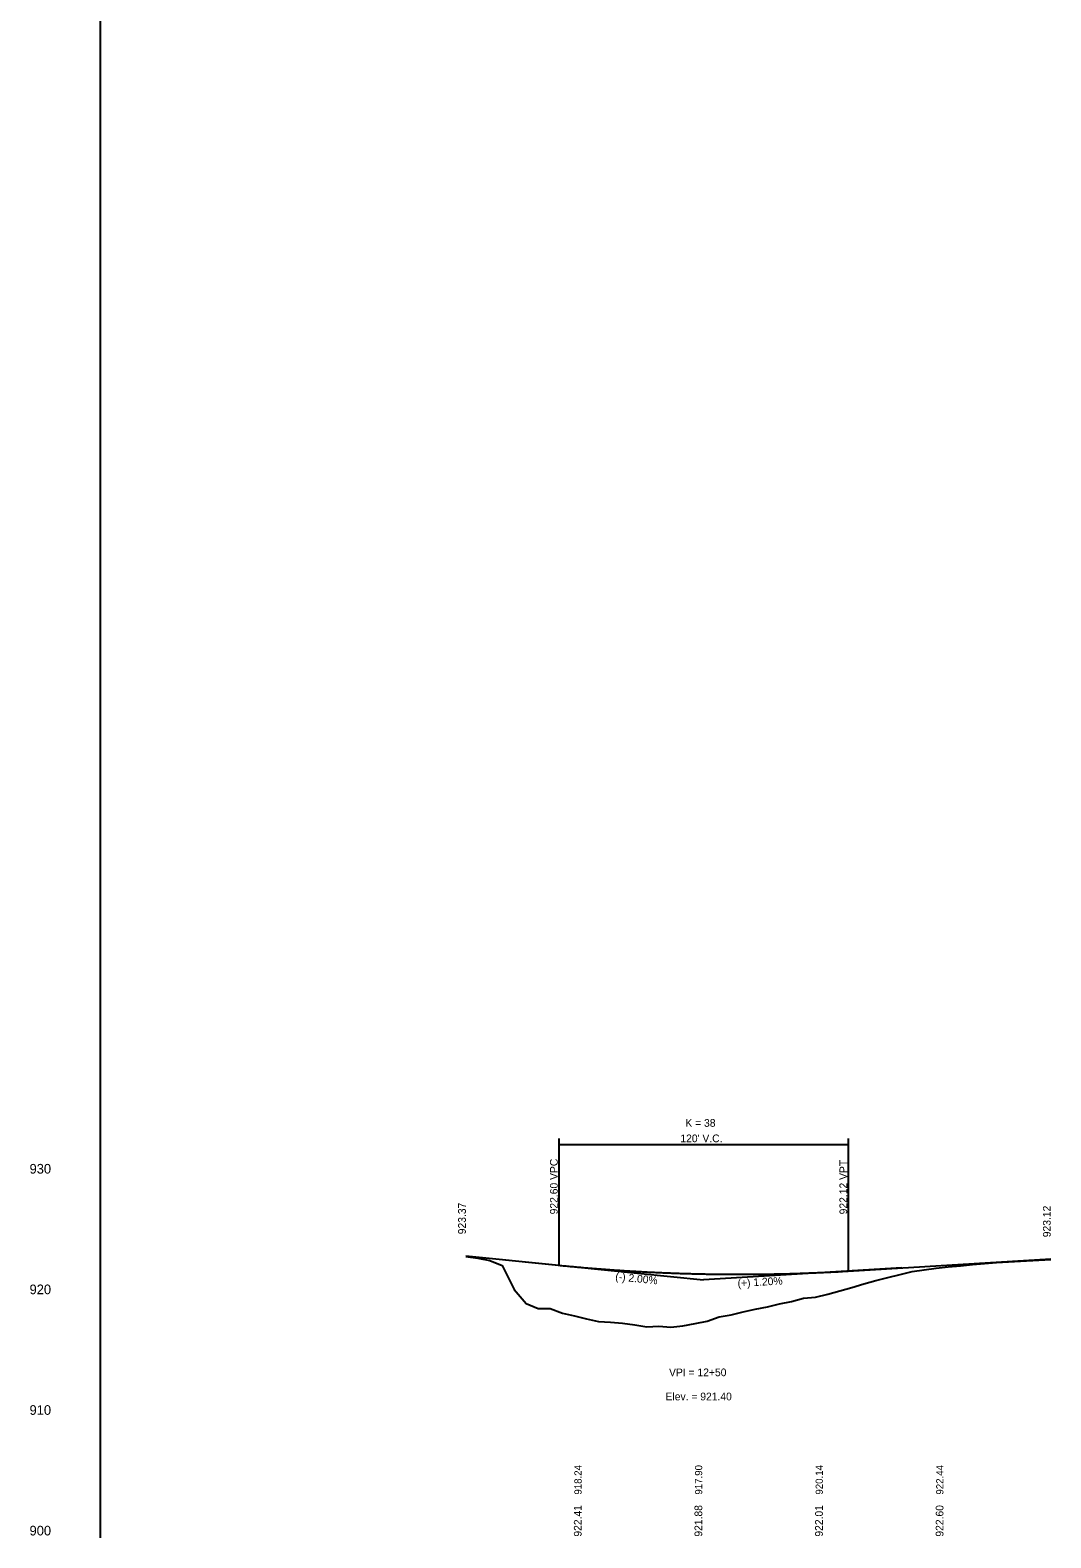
# Model space of a CAD drawing. Extents: x 1475774 to 1484571, y 1098511 to 1113011.
# Drawn here: x 1477542 to 1477965, y 1099761 to 1100386 of the extents above; entities that cross this region are included whole.
import ezdxf

# ---------------------------------------------------------------- set-up
doc = ezdxf.new("R2010")
doc.units = 0
for name, color, linetype in [('RD_DDB_ElevTX', 7, 'Continuous'), ('RD_DDB_GradeTX', 7, 'Continuous'), ('RD_DDB_Profile_EX', 7, 'Continuous'), ('RD_DDB_Profile_Lbl', 7, 'Continuous'), ('RD_DDB_Profile_PR', 7, 'Continuous'), ('RD_DDB_StripGrade', 7, 'Continuous'), ('RD_DDB_VCLbl', 7, 'Continuous'), ('RD_GPK_Profile_Cell', 7, 'Continuous')]:
    doc.layers.add(name, color=color, linetype=linetype)

msp = doc.modelspace()

# ---------------------------------------------------------------- linework, layer by layer
at = {"layer": 'RD_DDB_GradeTX'}
for p in [(1477738.99, 1099876.45), (1477903.24, 1099873.17)]:
    msp.add_line(p, (1477820.98, 1099868.25), dxfattribs=at)
at = {"layer": 'RD_DDB_Profile_EX'}
msp.add_lwpolyline([(1477722.49, 1099877.85), (1477727.49, 1099877.19), (1477732.49, 1099876.21), (1477737.49, 1099874.16), (1477742.49, 1099864.25), (1477747.49, 1099858.41), (1477752.49, 1099856.33), (1477757.49, 1099856.31), (1477762.49, 1099854.43), (1477767.49, 1099853.3), (1477772.49, 1099852.1), (1477777.49, 1099850.99), (1477782.49, 1099850.72), (1477787.49, 1099850.23), (1477792.49, 1099849.52), (1477797.49, 1099848.71), (1477802.49, 1099848.98), (1477807.49, 1099848.59), (1477812.49, 1099849.1), (1477817.49, 1099850.04), (1477822.49, 1099851.07), (1477827.49, 1099852.84), (1477832.49, 1099853.75), (1477837.49, 1099854.95), (1477842.49, 1099856.09), (1477847.49, 1099857.07), (1477852.49, 1099858.29), (1477857.49, 1099859.29), (1477862.49, 1099860.61), (1477867.49, 1099861.03), (1477872.49, 1099862.31), (1477877.49, 1099863.58), (1477882.49, 1099865.02), (1477887.49, 1099866.49), (1477892.49, 1099867.92), (1477897.49, 1099869.16), (1477902.49, 1099870.42), (1477907.49, 1099871.61), (1477912.49, 1099872.42), (1477917.49, 1099873.06), (1477922.49, 1099873.59), (1477927.49, 1099874.05), (1477932.49, 1099874.52), (1477937.49, 1099874.98), (1477942.49, 1099875.37), (1477947.49, 1099875.68), (1477952.49, 1099875.99), (1477957.49, 1099876.26), (1477962.49, 1099876.49), (1477965, 1099876.61)], dxfattribs=at)
at = {"layer": 'RD_DDB_Profile_PR'}
for p, q in [((1477722.49, 1099878.1), (1477760.98, 1099874.25)), ((1477880.98, 1099871.84), (1477964.93, 1099876.86))]:
    msp.add_line(p, q, dxfattribs=at)
msp.add_spline([(1477760.98, 1099874.25), (1477763.38, 1099874.01), (1477765.78, 1099873.78), (1477768.18, 1099873.56), (1477770.58, 1099873.35), (1477772.98, 1099873.14), (1477775.38, 1099872.95), (1477777.78, 1099872.76), (1477780.18, 1099872.57), (1477782.58, 1099872.4), (1477784.98, 1099872.23), (1477787.38, 1099872.07), (1477789.78, 1099871.92), (1477792.18, 1099871.78), (1477794.58, 1099871.64), (1477796.98, 1099871.51), (1477799.38, 1099871.39), (1477801.78, 1099871.28), (1477804.18, 1099871.17), (1477806.58, 1099871.07), (1477808.98, 1099870.98), (1477811.38, 1099870.9), (1477813.78, 1099870.82), (1477816.18, 1099870.76), (1477818.58, 1099870.7), (1477820.98, 1099870.65), (1477823.38, 1099870.6), (1477825.78, 1099870.56), (1477828.18, 1099870.54), (1477830.58, 1099870.51), (1477832.98, 1099870.5), (1477835.38, 1099870.49), (1477837.78, 1099870.5), (1477840.18, 1099870.51), (1477842.58, 1099870.52), (1477844.98, 1099870.55), (1477847.38, 1099870.58), (1477849.78, 1099870.62), (1477852.18, 1099870.67), (1477854.58, 1099870.72), (1477856.98, 1099870.78), (1477859.38, 1099870.86), (1477861.78, 1099870.93), (1477864.18, 1099871.02), (1477866.58, 1099871.11), (1477868.98, 1099871.21), (1477871.38, 1099871.32), (1477873.78, 1099871.44), (1477876.18, 1099871.56), (1477878.58, 1099871.7), (1477880.98, 1099871.84)], degree=3, dxfattribs=at)
at = {"layer": 'RD_DDB_VCLbl'}
for p, q in [((1477760.98, 1099926.75), (1477760.98, 1099874.25)), ((1477760.98, 1099924.25), (1477880.98, 1099924.25)), ((1477880.98, 1099926.75), (1477880.98, 1099871.84))]:
    msp.add_line(p, q, dxfattribs=at)
at = {"layer": 'RD_GPK_Profile_Cell'}
msp.add_line((1477570.98, 1099761.25), (1477570.98, 1101011.25), dxfattribs=at)

# ---------------------------------------------------------------- texts
at = {"layer": 'RD_DDB_ElevTX'}
for s, p in [('930', (1477541.62, 1099912.25)), ('930', (1477541.62, 1099912.25)), ('920', (1477541.62, 1099862.25)), ('920', (1477541.62, 1099862.25)), ('910', (1477541.62, 1099812.25)), ('910', (1477541.62, 1099812.25)), ('900', (1477541.62, 1099762.25)), ('900', (1477541.62, 1099762.25))]:
    msp.add_text(s, height=4, dxfattribs=at).set_placement(p)
at = {"layer": 'RD_DDB_GradeTX'}
for s, rotation, p in [('(-) 2.00%', 354.28941, (1477784.33, 1099868.07)), ('(+) 1.20%', 3.42228, (1477835.23, 1099865.19))]:
    msp.add_text(s, height=3.2, rotation=rotation, dxfattribs=at).set_placement(p)
at = {"layer": 'RD_DDB_Profile_Lbl'}
for s, p in [('923.37', (1477722.49, 1099887.1)), ('923.12', (1477964.93, 1099885.86))]:
    msp.add_text(s, height=3.2, rotation=90, dxfattribs=at).set_placement(p)
for s, p in [('VPI = 12+50', (1477806.73, 1099828.25)), ('Elev. = 921.40', (1477805.28, 1099818.25))]:
    msp.add_text(s, height=3.2, dxfattribs=at).set_placement(p)
at = {"layer": 'RD_DDB_StripGrade'}
for s, height, p in [('922.60 VPC', 3.2, (1477760.58, 1099895.35)), ('922.12 VPT', 3.2, (1477880.58, 1099895.35)), ('918.24', 3, (1477770.48, 1099779.17)), ('918.24', 3, (1477770.48, 1099779.17)), ('917.90', 3, (1477820.48, 1099779.17)), ('920.14', 3, (1477870.48, 1099779.17)), ('922.44', 3, (1477920.48, 1099779.17)), ('922.41', 3.2, (1477770.48, 1099761.75)), ('921.88', 3.2, (1477820.48, 1099761.75)), ('922.01', 3.2, (1477870.48, 1099761.75)), ('922.60', 3.2, (1477920.48, 1099761.75))]:
    msp.add_text(s, height=height, rotation=90, dxfattribs=at).set_placement(p)
at = {"layer": 'RD_DDB_VCLbl'}
for s, p in [('K = 38', (1477813.51, 1099931.65)), ("120' V.C.", (1477811.42, 1099925.25))]:
    msp.add_text(s, height=3.2, dxfattribs=at).set_placement(p)
at = {"layer": 'RD_GPK_Profile_Cell'}
for s, p in [('230', (1477570.98, 1099761.32)), ('900', (1477570.98, 1099761.29)), ('50', (1477570.98, 1099761.28)), ('RIGRELOC', (1477570.98, 1099761.31)), ('1000.000000', (1477570.98, 1099761.3)), ('10', (1477570.98, 1099761.27)), ('NOGAP', (1477570.98, 1099761.26))]:
    msp.add_text(s, height=0.00975, dxfattribs=at).set_placement(p)

doc.saveas('drawing.dxf')
